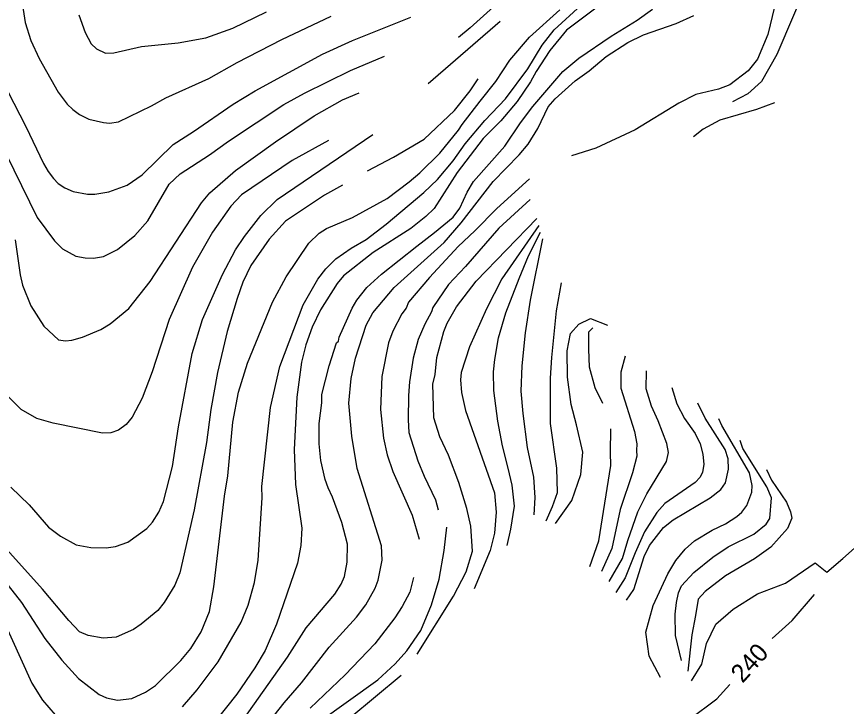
# Model space of a CAD drawing. Extents: x -555860 to -552701, y -1187050 to -1182291.
# Drawn here: x -555576.4 to -555120.4, y -1183028.5 to -1182649.5 of the extents above; entities that cross this region are included whole.
import ezdxf

# ---------------------------------------------------------------- set-up
doc = ezdxf.new("R2010")
doc.units = 0
doc.layers.add('Level 40', color=7, linetype='Continuous')
doc.layers.add('Level 41', color=7, linetype='Continuous')

msp = doc.modelspace()

# ---------------------------------------------------------------- linework, layer by layer
at = {"layer": 'Level 40'}
for points in [[(-555305.36, -1182635.88), (-555327.09, -1182655.63), (-555333.54, -1182660.95)], [(-555251.59, -1182639.69), (-555274.31, -1182656.91), (-555283.34, -1182668.05), (-555290.82, -1182679.62), (-555293.93, -1182685.41), (-555301.26, -1182696.13), (-555310.3, -1182706.72), (-555320.03, -1182716.46), (-555334.29, -1182735.22), (-555346.96, -1182754.83), (-555351.49, -1182759.36), (-555359.83, -1182765.99), (-555380.43, -1182779.11), (-555396.66, -1182791.95), (-555400.19, -1182796.19), (-555409.36, -1182810.58), (-555414.02, -1182820.18), (-555417.4, -1182829.77), (-555419.8, -1182839.37), (-555422.48, -1182858.56), (-555423.89, -1182887.35), (-555423.19, -1182906.54), (-555419.66, -1182930.53), (-555420.22, -1182940.13), (-555422.06, -1182949.72), (-555433.49, -1182983.31), (-555439.84, -1182997.7), (-555445.48, -1183007.3), (-555455.36, -1183021.69), (-555466.65, -1183036.08)], [(-555542.15, -1182648.58), (-555538.62, -1182658.18), (-555535.38, -1182664.52), (-555532.55, -1182667.21), (-555527.47, -1182669.61), (-555522.96, -1182669.47), (-555507.72, -1182665.94), (-555487.68, -1182663.96), (-555472.44, -1182661.14), (-555457.48, -1182655.78), (-555439.13, -1182646.89)], [(-555160, -1182696.89), (-555169.83, -1182700.61), (-555189.96, -1182706.4), (-555199.08, -1182711.33), (-555204.45, -1182715.59)], [(-555404.91, -1182717.54), (-555425.02, -1182728.59), (-555452.82, -1182747.36), (-555458.61, -1182753.57), (-555468.77, -1182767.96), (-555479.64, -1182787.16), (-555492.62, -1182815.94), (-555501.93, -1182844.73), (-555507.29, -1182859.12), (-555512.8, -1182869.57), (-555516.18, -1182873.52), (-555520.42, -1182876.62), (-555524.65, -1182878.18), (-555529.17, -1182878.32), (-555556.26, -1182872.81), (-555565.29, -1182870.27), (-555573.9, -1182865.33), (-555580.96, -1182858.28)], [(-555356.23, -1182999.78), (-555336.31, -1182967.81), (-555329.29, -1182954.48), (-555325.91, -1182943.24), (-555326.81, -1182929.4), (-555329.06, -1182919.8), (-555333.44, -1182905.41), (-555339.08, -1182890.45), (-555343.74, -1182880.29), (-555347.13, -1182869.83), (-555347.68, -1182851.36), (-555346.46, -1182846.15), (-555345.43, -1182836.69), (-555341.62, -1182822.43), (-555339.79, -1182817.92), (-555334.57, -1182808.89), (-555323.84, -1182794.78), (-555290.54, -1182760.49)], [(-555280.24, -1182927.96), (-555271.26, -1182915.26), (-555266.32, -1182901.1), (-555265.25, -1182888.79), (-555268.67, -1182873.8), (-555271.63, -1182862.51), (-555273.76, -1182847.54), (-555273.79, -1182833.12), (-555272.1, -1182823.66), (-555267.46, -1182818.38), (-555260.96, -1182815.43), (-555251.74, -1182819.02)], [(-555241.28, -1182970.12), (-555237.14, -1182964.25), (-555231.55, -1182946.05), (-555228.59, -1182939.98), (-555220.97, -1182930.11), (-555215.61, -1182926.01), (-555195.29, -1182913.88), (-555189.45, -1182909.33), (-555186.82, -1182905.69), (-555185.12, -1182898.07), (-555185.41, -1182892.43), (-555187.02, -1182887.39), (-555198.09, -1182870.16), (-555201.98, -1182861.77)], [(-555161.13, -1182991.23), (-555150.17, -1182981.18), (-555137.91, -1182967.07)], [(-555365.1, -1183011.47), (-555393.18, -1183034.88), (-555416.56, -1183053.16), (-555429.68, -1183066.56), (-555440.97, -1183081.52), (-555446.47, -1183091.4), (-555451.41, -1183104.95), (-555455.79, -1183123.01), (-555458.69, -1183139.02), (-555462.94, -1183153.47), (-555473.48, -1183179.96)], [(-555206.88, -1183035.59), (-555191.59, -1183024.3), (-555184.47, -1183016.4)]]:
    msp.add_lwpolyline(points, dxfattribs=at)
at = {"layer": 'Level 41'}
for points in [[(-555127.76, -1182600.84), (-555133.77, -1182605.76), (-555143.1, -1182610.69), (-555151.64, -1182617.83), (-555156.2, -1182628.82), (-555163.68, -1182659.3), (-555169.32, -1182672.85), (-555174.4, -1182679.34), (-555184.56, -1182686.96), (-555190.77, -1182689.36), (-555203.19, -1182692.32), (-555212.5, -1182697.12), (-555236.43, -1182711.72), (-555258.02, -1182721.83), (-555271.52, -1182726.03)], [(-555124.51, -1182608.82), (-555133.9, -1182617.63), (-555140.38, -1182627.31), (-555158.74, -1182670.31), (-555167.06, -1182685.05), (-555174.66, -1182691.94), (-555183.01, -1182696.38)], [(-555574.32, -1182634.75), (-555571.64, -1182652.81), (-555568.54, -1182662.69), (-555563.88, -1182672.57), (-555553.58, -1182690.91), (-555548.64, -1182697.55), (-555545.39, -1182700.57), (-555541.88, -1182703.34), (-555536.63, -1182705.82), (-555528.6, -1182707.71), (-555525.38, -1182707.98), (-555520.42, -1182707.28), (-555502.21, -1182698.53), (-555494.45, -1182694.16), (-555470.74, -1182683.43), (-555455.22, -1182674.69), (-555430.67, -1182661.99), (-555403.57, -1182649.28)], [(-555580.96, -1182962), (-555573.62, -1182971.45), (-555560.92, -1182991.21), (-555551.6, -1183003.06), (-555542.29, -1183013.08), (-555531, -1183021.83), (-555526.91, -1183023.81), (-555520.98, -1183025.08), (-555513.08, -1183024.09), (-555505.46, -1183020.7), (-555500.1, -1183017.03), (-555486.13, -1183003.2), (-555480.62, -1182996.71), (-555474.98, -1182987.54), (-555470.46, -1182976.25), (-555467.92, -1182962.7), (-555462.14, -1182913.03), (-555460.3, -1182901.74), (-555457.62, -1182872.39), (-555454.38, -1182855.88), (-555449.44, -1182839.93), (-555435.75, -1182806.35), (-555428.27, -1182792.52), (-555415.71, -1182774.03), (-555410.06, -1182768.39), (-555406.11, -1182765.85), (-555391.86, -1182759.78), (-555372.81, -1182749.34), (-555360.67, -1182740.3), (-555354.75, -1182735.23), (-555343.88, -1182724.5), (-555333.58, -1182711.94), (-555331.6, -1182708.84), (-555321.74, -1182695.9), (-555313.13, -1182685.1), (-555305.36, -1182673.42), (-555294.63, -1182660.86), (-555277.84, -1182645.76)], [(-555485.28, -1183028.75), (-555477.09, -1183019.43), (-555465.66, -1183003.91), (-555452.96, -1182982.18), (-555449.15, -1182972.86), (-555445.62, -1182960.45), (-555443.65, -1182948.03), (-555441.39, -1182913.88), (-555441.67, -1182907.67), (-555436.88, -1182864.21), (-555431.8, -1182841.63), (-555418.95, -1182807.76), (-555410.91, -1182793.65), (-555406.4, -1182788), (-555400.89, -1182782.64), (-555392.57, -1182776.71), (-555384.38, -1182771.91), (-555373.37, -1182763.59), (-555352.63, -1182746.09), (-555345.01, -1182738.89), (-555336.4, -1182728.73), (-555329.91, -1182719.42), (-555319.05, -1182706.58), (-555307.76, -1182694.72), (-555295.5, -1182678.09), (-555287.62, -1182665.25), (-555280.94, -1182656.76), (-555266.13, -1182643.22)], [(-555408.65, -1182857.15), (-555404.56, -1182841.34), (-555400.61, -1182828.64), (-555399.48, -1182827.8), (-555399.06, -1182825.54), (-555392, -1182809.73), (-555389.46, -1182805.22), (-555383.96, -1182798.3), (-555375.91, -1182790.97), (-555356.44, -1182775.58), (-555346.67, -1182768.11), (-555336.4, -1182759.64), (-555332.87, -1182754.7), (-555328.87, -1182745.93), (-555325.25, -1182740.16), (-555308.18, -1182720.69), (-555299.57, -1182707.85), (-555292.66, -1182698.96), (-555276.15, -1182679.62), (-555267.4, -1182672.29), (-555249.76, -1182660.29), (-555235.36, -1182651.4), (-555226.9, -1182645.33)], [(-555591.26, -1182671.44), (-555571.22, -1182709.82), (-555561.62, -1182730.14), (-555558.94, -1182734.66), (-555556.17, -1182738.34), (-555553.44, -1182741.15), (-555549.89, -1182743.59), (-555545.25, -1182745.53), (-555537.35, -1182747.08), (-555533.4, -1182747.08), (-555525.78, -1182745.81), (-555515.62, -1182742.14), (-555507.44, -1182736.35), (-555490.36, -1182719.7), (-555479.14, -1182712.65), (-555457.34, -1182697.55), (-555445.34, -1182690.35), (-555408.37, -1182670.03), (-555391.86, -1182662.69), (-555359.69, -1182649.71)], [(-555434.76, -1183033.54), (-555429.4, -1183026.49), (-555419.8, -1183015.48), (-555404.56, -1182995.87), (-555389.6, -1182979.36), (-555384.52, -1182972.58), (-555379.44, -1182963.55), (-555377.75, -1182959.03), (-555375.49, -1182948.15), (-555375.78, -1182940.27), (-555389.18, -1182897.79), (-555392.14, -1182880.01), (-555393.84, -1182861.95), (-555392.57, -1182848.4), (-555390.17, -1182837.11), (-555384.38, -1182819.05), (-555380.57, -1182812.27), (-555369, -1182798.3), (-555341.48, -1182773.61), (-555332.03, -1182762.74), (-555314.53, -1182740.16), (-555300.28, -1182725.49), (-555295.34, -1182719.56), (-555289.97, -1182710.95), (-555284.33, -1182699.1), (-555280.47, -1182694.59), (-555269.51, -1182684.85), (-555261.75, -1182679.2), (-555252.44, -1182671.44), (-555240.44, -1182663.68), (-555231.98, -1182659.59), (-555213.91, -1182653.24), (-555204.32, -1182648.86)], [(-555350.2, -1182686.32), (-555310.66, -1182651.92)], [(-555595.07, -1182698.82), (-555565.15, -1182759.78), (-555555.56, -1182772.76), (-555551.18, -1182776.99), (-555543.84, -1182781.09), (-555538.76, -1182782.07), (-555534.13, -1182782.27), (-555528.6, -1182781.23), (-555520.98, -1182777.42), (-555511.39, -1182769.66), (-555504.19, -1182761.75), (-555492.49, -1182741.6), (-555486.44, -1182735.86), (-555470.46, -1182725.35), (-555460.02, -1182717.87), (-555429.54, -1182697.83), (-555418.25, -1182691.62), (-555392.85, -1182679.06), (-555374.23, -1182671.27)], [(-555383.57, -1182734.2), (-555369.28, -1182726.76), (-555352.35, -1182716.74), (-555335.7, -1182701.07), (-555327.23, -1182690.35), (-555322.71, -1182683.72)], [(-555577.15, -1182772.2), (-555574.46, -1182791.39), (-555573.05, -1182797.03), (-555568.54, -1182808.32), (-555561.34, -1182819.47), (-555553.28, -1182827.05), (-555549.5, -1182827.54), (-555546.09, -1182827.18), (-555540.17, -1182825.54), (-555530.01, -1182821.31), (-555524.93, -1182818.34), (-555514.77, -1182809.87), (-555503.06, -1182795.06), (-555474.84, -1182751.88), (-555470.18, -1182746.23), (-555456.07, -1182734.09), (-555434.05, -1182718.29), (-555412.89, -1182704.04), (-555397.22, -1182695.15), (-555388.19, -1182691.34)], [(-555579.55, -1182908.09), (-555569.55, -1182917.65), (-555558.76, -1182930.05), (-555552.33, -1182934.87), (-555543.58, -1182939.69), (-555535.66, -1182941.11), (-555527.19, -1182941.25), (-555522.11, -1182940.55), (-555515.34, -1182938.15), (-555504.89, -1182930.81), (-555501.65, -1182927.28), (-555498.26, -1182921.78), (-555495.58, -1182915.85), (-555490.78, -1182896.66), (-555487.4, -1182874.93), (-555479.92, -1182834.57), (-555474.27, -1182815.94), (-555463.27, -1182791.11), (-555456.07, -1182777.7), (-555451.13, -1182770.36), (-555442.1, -1182758.79), (-555433.21, -1182750.04), (-555380.7, -1182714.23)], [(-555294.58, -1182738.6), (-555312.48, -1182754.84), (-555324.55, -1182767.12), (-555333.72, -1182775.86), (-555349.53, -1182792.8), (-555360.96, -1182806.35), (-555362.37, -1182809.73), (-555364.77, -1182812.84), (-555369.7, -1182822.29), (-555372.1, -1182828.64), (-555375.77, -1182847.27), (-555376.34, -1182865.33), (-555374.79, -1182881.14), (-555372.81, -1182890.17), (-555369.56, -1182899.48), (-555358.98, -1182923.47), (-555355.17, -1182936.6)], [(-555397.22, -1182742.14), (-555407.24, -1182747.64), (-555428.55, -1182761.9), (-555437.58, -1182771.77), (-555447.6, -1182786.31), (-555451.98, -1182795.34), (-555455.22, -1182804.37), (-555460.58, -1182822.44), (-555465.95, -1182845.01), (-555469.61, -1182865.33), (-555472.01, -1182883.4), (-555478.79, -1182920.42), (-555486.69, -1182955.08), (-555489.51, -1182961.86), (-555495.3, -1182971.45), (-555498.83, -1182975.69), (-555507.86, -1182983.31), (-555512.05, -1182986.21), (-555521.69, -1182990.36), (-555528.88, -1182990.93), (-555537, -1182989.42), (-555541.72, -1182987.54), (-555547.65, -1182981.33), (-555562.19, -1182963.97), (-555593.37, -1182929.4)], [(-555294.17, -1182749.99), (-555311.34, -1182765.75), (-555329.63, -1182786.73), (-555339.08, -1182796.61), (-555347.69, -1182809.31), (-555348.4, -1182811.71), (-555352.07, -1182818.48), (-555355.73, -1182826.95), (-555358.42, -1182837.11), (-555360.53, -1182850.09), (-555361.1, -1182857.71), (-555361.19, -1182870.95), (-555360.82, -1182878.03), (-555355.88, -1182893.56), (-555352.49, -1182902.02), (-555346.14, -1182915.01), (-555344.71, -1182920.42)], [(-555289.49, -1182764.21), (-555309.76, -1182793.47), (-555318.23, -1182810.01), (-555327.51, -1182830.9), (-555332.03, -1182845.01), (-555332.45, -1182848.97), (-555331.89, -1182856.02), (-555329.77, -1182865.9), (-555313.82, -1182911.05), (-555312.89, -1182921.73), (-555313.84, -1182933.23), (-555316.08, -1182942.8), (-555324.96, -1182963.85)], [(-555306.76, -1182940.14), (-555304.76, -1182931.12), (-555302.77, -1182918.46), (-555303.99, -1182906.85), (-555306.18, -1182897.51), (-555309.39, -1182885.25), (-555311.99, -1182871.82), (-555314.1, -1182854.89), (-555314.39, -1182844.73), (-555313.54, -1182837.96), (-555311.57, -1182826.02), (-555307.5, -1182812.31), (-555300.3, -1182793.39), (-555295.12, -1182780.94), (-555288.45, -1182767.93)], [(-555287.41, -1182771.66), (-555294.13, -1182805.35), (-555296.93, -1182823.27), (-555298.79, -1182841.4), (-555299.23, -1182855.27), (-555298.16, -1182867.59), (-555295.9, -1182886.22), (-555292.37, -1182902.59), (-555291.64, -1182913.64), (-555292.12, -1182923.19)], [(-555285.38, -1182926.49), (-555281.91, -1182918.58), (-555279.17, -1182910.86), (-555279.56, -1182897.64), (-555282.92, -1182872.95), (-555282.92, -1182848.12), (-555282.3, -1182836.71), (-555279.73, -1182811.13), (-555276.92, -1182795.83)], [(-555254.29, -1182861.96), (-555258.4, -1182853.41), (-555261.52, -1182842.09), (-555262.01, -1182832.17), (-555262.03, -1182822.7), (-555259.7, -1182820.53)], [(-555242.02, -1182836.05), (-555244.35, -1182844.86), (-555244.33, -1182853.71), (-555236.77, -1182877.47), (-555235.5, -1182884.24), (-555235.7, -1182887.88), (-555235.65, -1182891.02), (-555237.9, -1182900.05), (-555244.82, -1182920.37), (-555249.26, -1182941.72), (-555254.94, -1182954.33)], [(-555250.7, -1182959.83), (-555243.41, -1182947.18), (-555240.58, -1182937.3), (-555234.94, -1182921.5), (-555230.14, -1182911.62), (-555219.28, -1182893.84), (-555218.15, -1182889.04), (-555219.13, -1182883.96), (-555223.8, -1182871.53), (-555227.55, -1182863.46), (-555230.36, -1182853.99), (-555230.18, -1182844.01)], [(-555459.31, -1183046.39), (-555427.56, -1183001.37), (-555417.26, -1182985.28), (-555401.6, -1182966.8), (-555398.07, -1182961.29), (-555396.23, -1182957.06), (-555394.68, -1182949.16), (-555394.54, -1182939.28), (-555397.65, -1182927.43), (-555402.87, -1182913.59), (-555405.11, -1182908.31), (-555406.82, -1182903.72), (-555409.19, -1182893.28), (-555410.06, -1182884.24), (-555410.2, -1182872.95), (-555408.65, -1182861.66), (-555408.65, -1182857.15)], [(-555216.32, -1182853.2), (-555213.64, -1182862.26), (-555209.43, -1182870.33), (-555203.47, -1182878.6), (-555200.79, -1182884.24), (-555199.24, -1182889.89), (-555198.81, -1182895.53), (-555199.52, -1182899.77), (-555200.83, -1182902.47), (-555203.47, -1182905.41), (-555220.12, -1182916.98), (-555224.5, -1182921.92), (-555231.27, -1182932.5), (-555236.58, -1182944.07), (-555241.99, -1182957.91), (-555247.19, -1182965.9)], [(-555222.56, -1183012.53), (-555228.86, -1183000.89), (-555230.55, -1182987.62), (-555226.56, -1182972.96), (-555218.57, -1182955.65), (-555214.2, -1182948.31), (-555209, -1182942.02), (-555203.89, -1182937.44), (-555194.16, -1182931.66), (-555186.82, -1182928.13), (-555180.61, -1182924.18), (-555177.93, -1182921.78), (-555175.11, -1182918.11), (-555172.42, -1182910.77), (-555172.28, -1182907.1), (-555173.7, -1182900.05), (-555188.96, -1182874.1), (-555190.43, -1182870.43)], [(-555261.38, -1182951.59), (-555256.44, -1182937.42), (-555249.9, -1182896.1), (-555250.04, -1182889.04), (-555249.84, -1182875.99)], [(-555210.98, -1183003.29), (-555214.27, -1182989.53), (-555214.48, -1182977.72), (-555213.76, -1182971.45), (-555212.66, -1182966.1), (-555211.09, -1182962.14), (-555204.32, -1182954.94), (-555193.88, -1182946.48), (-555185.41, -1182940.83), (-555171.3, -1182933.77), (-555164.52, -1182928.27), (-555162.55, -1182925.17), (-555161.67, -1182913.86), (-555164.17, -1182907.8), (-555177.28, -1182886.82), (-555178.79, -1182882.34)], [(-555164.37, -1182898.39), (-555161.53, -1182904.22), (-555153.25, -1182916.34), (-555151.06, -1182921.48), (-555150.49, -1182925.09), (-555152.81, -1182930.81), (-555161.98, -1182940.97), (-555171.01, -1182947.32), (-555186.82, -1182956.64), (-555198.11, -1182965.24), (-555201.92, -1182969.48), (-555203.41, -1182978.43), (-555205.42, -1182989.14), (-555207.55, -1183009.05)], [(-555410.2, -1183036.93), (-555377.89, -1183013.93), (-555368.29, -1183005.04), (-555361.94, -1182997.98), (-555354.32, -1182986.69), (-555348.4, -1182972.58), (-555344.16, -1182958.47), (-555341.48, -1182942.81), (-555339.99, -1182929.96)], [(-555205.56, -1183014.43), (-555199.83, -1183005.3), (-555197.27, -1182993.85), (-555192.12, -1182983.31), (-555182.71, -1182974.99), (-555169.25, -1182966.65), (-555153.93, -1182960.71), (-555137.52, -1182949.6), (-555131.23, -1182954.76), (-555122.3, -1182947.28), (-555104.8, -1182931.61)], [(-555358.28, -1182957.72), (-555360.39, -1182965.67), (-555364.48, -1182973.57), (-555368.58, -1182979.78), (-555379.58, -1182994.03), (-555395.81, -1183011.11), (-555415.15, -1183029.45)], [(-555584.77, -1182978.51), (-555567.97, -1183015.76), (-555562.19, -1183025.08), (-555551.74, -1183037.07)]]:
    msp.add_lwpolyline(points, dxfattribs=at)

# ---------------------------------------------------------------- texts
at = {"layer": 'Level 40'}
msp.add_text('240', height=10, rotation=47.989, dxfattribs=at).set_placement((-555177.47, -1183016.09))

doc.saveas('drawing.dxf')
